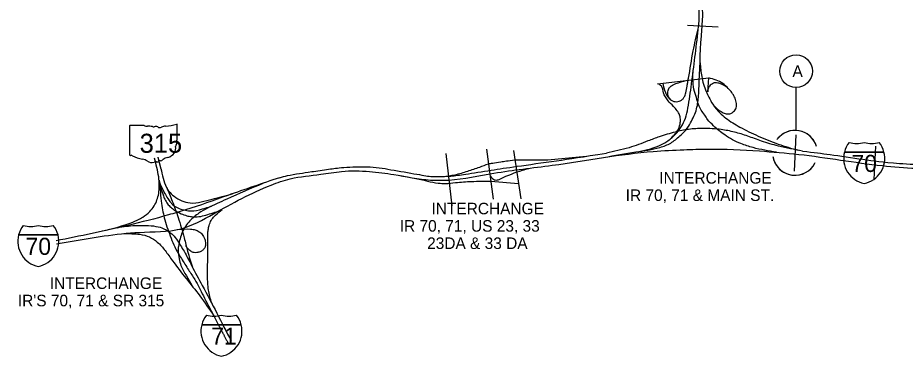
# Model space of a CAD drawing. Extents: x -13 to 322, y -402 to 112.
# Drawn here: x -2.76 to 6.02, y 97.23 to 100.58 of the extents above; entities that cross this region are included whole.
import ezdxf

# ---------------------------------------------------------------- set-up
doc = ezdxf.new("R2010")
doc.units = 0
for name, color, linetype in [('GM_X_Interstate_Shield', 7, 'Continuous'), ('GM_X_State_Shield', 7, 'Continuous'), ('SC_Scratch1', 7, 'Continuous'), ('SH_Data', 7, 'Continuous'), ('SH_Text', 7, 'Continuous')]:
    doc.layers.add(name, color=color, linetype=linetype)

msp = doc.modelspace()

# ---------------------------------------------------------------- linework, layer by layer
at = {"layer": 'GM_X_Interstate_Shield'}
for p, q in [((5.4189, 99.2528), (5.8101, 99.2528)), ((5.8101, 99.2528), (5.4189, 99.2528)), ((5.8101, 99.2528), (5.4189, 99.2528)), ((-2.7567, 98.4325), (-2.3655, 98.4325)), ((-2.3655, 98.4325), (-2.7567, 98.4325)), ((-2.3655, 98.4325), (-2.7567, 98.4325)), ((-0.9437, 97.5438), (-0.5525, 97.5438)), ((-0.5525, 97.5438), (-0.9437, 97.5438)), ((-0.5525, 97.5438), (-0.9437, 97.5438))]:
    msp.add_line(p, q, dxfattribs=at)
for centre, start, end in [((5.6653, 99.1905), 141.66896, 165.80665), ((5.5402, 99.5912), 253.00908, 286.99093), ((5.6888, 99.5912), 253.00908, 286.99093), ((5.5637, 99.1905), 14.19335, 38.33104), ((5.6653, 99.1905), 165.80665, 258.46304), ((5.5637, 99.1905), 281.53696, 14.19335), ((-2.5103, 98.3702), 141.66896, 165.80665), ((-2.6354, 98.771), 253.00908, 286.99093), ((-2.4868, 98.771), 253.00908, 286.99093), ((-2.612, 98.3702), 14.19335, 38.33104), ((-2.5103, 98.3702), 165.80665, 258.46304), ((-2.612, 98.3702), 281.53696, 14.19335), ((-0.6972, 97.4815), 141.66896, 165.80665), ((-0.8224, 97.8823), 253.00908, 286.99093), ((-0.6738, 97.8823), 253.00908, 286.99093), ((-0.7989, 97.4815), 14.19335, 38.33104), ((-0.6972, 97.4815), 165.80665, 258.46304), ((-0.7989, 97.4815), 281.53696, 14.19335)]:
    msp.add_arc(centre, 0.2542, start, end, dxfattribs=at)
at = {"layer": 'GM_X_State_Shield'}
for p, q in [((-1.6568, 99.5119), (-1.6568, 99.2254)), ((-1.514, 99.5168), (-1.6522, 99.5168)), ((-1.185, 99.374), (-1.185, 99.5239)), ((-1.185, 99.3741), (-1.185, 99.374))]:
    msp.add_line(p, q, dxfattribs=at)
for centre, major_axis, start_param, end_param in [((-1.6514, 99.5125), (0.00547, 0), 1.712693, 3.28349), ((-1.4811, 99.5501), (0.053, 0), 4.042523, 4.731795), ((-1.4635, 99.3559), (0.1904, 0), 1.404758, 1.657858), ((-1.4203, 99.514), (0.0153, 0), 3.836095, 5.185415), ((-1.3978, 99.4808), (0.0318, 0), 0.950623, 2.079405), ((-1.3568, 99.5263), (0.0383, 0), 4.081561, 5.145723), ((-1.2892, 99.4293), (0.1007, 0), 1.699011, 2.107814), ((-1.3531, 99.9074), (0.5004, 0), 4.814394, 5.042369), ((-1.1902, 99.5245), (0.00525, 0), 6.141152, 7.989035), ((-1.1862, 99.363), (0.00813, 0), 1.883978, 3.671073), ((-1.1906, 99.3734), (0.00562, 0), 5.05454, 6.418171), ((-1.325, 99.2922), (0.1252, 0), 5.101752, 6.440018), ((-1.1661, 99.3113), (0.0355, 0), 2.387724, 3.262537), ((-1.2379, 99.3441), (0.0488, 0), 5.934695, 6.695948), ((-1.6514, 99.2247), (0.00552, 0), 3.00124, 4.508301), ((-1.6505, 99.254), (0.0421, 0), 4.665946, 4.897461), ((-1.6419, 99.2088), (0.0152, 0), 0.519207, 1.627899), ((-1.4503, 99.4662), (0.3614, 0), 4.195997, 4.488961), ((-1.2722, 99.1449), (0.0685, 0), 1.647645, 2.488434), ((-1.5581, 99.0966), (0.1131, 0), 0.823519, 1.323587), ((-1.4358, 99.2074), (0.0717, 0), 4.026481, 4.996735), ((-1.3943, 99.1083), (0.059, 0), 1.495662, 1.94098), ((-1.3891, 99.1859), (0.0382, 0), 4.691044, 5.507374), ((-1.3545, 99.1582), (0.0108, 0), 1.147584, 2.315152), ((-1.3591, 99.1976), (0.0404, 0), 4.937069, 5.64225)]:
    msp.add_ellipse(centre, major_axis=major_axis, ratio=0.8, start_param=start_param, end_param=end_param, dxfattribs=at)
at = {"layer": 'SC_Scratch1'}
for p, q in [((3.8643, 100.5081), (4.1678, 100.4907)), ((4.9386, 99.4251), (4.9196, 99.0654)), ((1.8765, 99.2808), (1.9403, 98.7879)), ((5.7276, 99.3108), (5.7101, 98.9807)), ((1.4733, 99.2382), (1.5339, 98.721)), ((2.1433, 99.267), (2.217, 98.7916))]:
    msp.add_line(p, q, dxfattribs=at)
at = {"layer": 'SH_Data'}
for p, q in [((3.5691, 99.9286), (4.0757, 99.9866)), ((4.0653, 99.8493), (4.0757, 99.9866)), ((2.4821, 99.1771), (2.8628, 99.2116)), ((2.1572, 99.1772), (2.4821, 99.1771)), ((1.9172, 98.9666), (2.1936, 98.9429))]:
    msp.add_line(p, q, dxfattribs=at)
msp.add_lwpolyline([(4.94, 99.4671), (4.94, 99.8923)], dxfattribs=at)
msp.add_circle((4.94, 100.0535), 0.1612, dxfattribs=at)
for start, end in [(16.48105, 141.99166), (19.89812, 139.38655), (143.15405, 143.91896), (189.64144, 334.30322), (196.86832, 332.2344)]:
    msp.add_arc((4.9291, 99.2452), 0.2221, start, end, dxfattribs=at)
for points in [[(3.9713, 100.4643), (3.9818, 100.5824), (3.9714, 100.7456), (3.9442, 101.0053)], [(3.0353, 99.2003), (3.3547, 99.2543), (3.5926, 99.299), (3.6997, 99.3426), (3.7893, 99.4124), (3.851, 99.4734), (3.8951, 99.5416), (3.9552, 99.6805), (3.9748, 99.8131), (3.9812, 99.9553), (4.0059, 100.4624)], [(3.3547, 99.2543), (3.5809, 99.3152), (3.6597, 99.3576), (3.7444, 99.426), (3.8024, 99.5034), (3.8456, 99.5889), (3.8693, 99.687), (3.9053, 99.9266), (3.9391, 100.1908), (3.9713, 100.4643)], [(3.6197, 99.9343), (3.6472, 99.8428), (3.6713, 99.8001), (3.6927, 99.7753), (3.7161, 99.7594), (3.743, 99.7519), (3.7695, 99.7519), (3.7933, 99.7602), (3.816, 99.7756), (3.8331, 99.798), (3.8495, 99.8382), (3.8621, 99.9042), (3.8673, 99.9425), (3.875, 99.9842), (3.922, 100.2543), (3.9722, 100.4737)], [(3.99, 100.136), (4.0066, 99.9992), (4.0491, 99.8526), (4.0764, 99.7952), (4.1148, 99.7282), (4.1838, 99.6423), (4.245, 99.5895), (4.3843, 99.5004), (4.5646, 99.4119), (4.7641, 99.3312), (4.9607, 99.2717)], [(4.7464, 99.2512), (4.514, 99.297), (4.3938, 99.3368), (4.2333, 99.4231), (4.1237, 99.5128), (4.0643, 99.5766), (4.0355, 99.618), (3.9743, 99.7223), (3.9589, 99.7747), (3.9353, 99.8523), (3.92, 99.9484), (3.9207, 100.0445)], [(4.1213, 99.7183), (4.1762, 99.6663), (4.2192, 99.6422), (4.258, 99.6309), (4.2933, 99.6342), (4.3217, 99.6536), (4.3473, 99.6902), (4.3473, 99.7481), (4.3313, 99.7964), (4.3047, 99.8413), (4.2695, 99.8822), (4.2144, 99.9326), (4.0757, 99.9866)], [(3.7004, 99.3866), (3.7757, 99.4829), (3.7943, 99.5443), (3.7943, 99.5918), (3.7815, 99.6324), (3.7634, 99.6612), (3.7254, 99.7053), (3.673, 99.7614), (3.6465, 99.8), (3.6272, 99.8386), (3.6071, 99.9055), (3.5691, 99.9286)], [(3.7035, 99.7665), (3.6788, 99.7999), (3.6704, 99.8268), (3.6704, 99.85), (3.6774, 99.8737), (3.695, 99.8988), (3.7229, 99.9183), (3.7762, 99.9396), (3.8487, 99.9606)], [(4.1294, 99.9365), (4.0986, 99.9212), (4.0724, 99.8879), (4.0653, 99.8493)], [(4.2606, 99.8922), (4.21, 99.9212), (4.1759, 99.9341), (4.1528, 99.9379), (4.135, 99.9379), (4.1294, 99.9365)], [(5.0035, 99.2628), (4.7647, 99.3128), (4.5984, 99.3617), (4.4617, 99.4107), (4.33, 99.4503), (4.2001, 99.4757), (4.0195, 99.4866), (3.876, 99.4773), (3.7426, 99.4503), (3.5865, 99.4048), (3.4743, 99.3626), (3.2869, 99.2959), (3.0623, 99.2434)], [(3.0353, 99.2003), (3.5265, 99.2595), (3.8298, 99.2759), (4.0647, 99.2826), (4.5776, 99.2636), (4.9676, 99.2301), (5.7941, 99.1189), (6.128, 99.0921), (6.8877, 99.0604), (7.4588, 99.0399), (8.2632, 99.0023), (9.2422, 98.9359)], [(-2.3825, 98.3436), (-1.9076, 98.4228), (-1.5627, 98.4586), (-1.1481, 98.4944), (-0.8277, 98.6414), (-0.2567, 98.926), (-0.0663, 98.9882), (0.2352, 99.0334), (0.4417, 99.0612), (0.7186, 99.0612), (0.9568, 99.031), (1.3227, 98.9765), (1.5029, 98.9765), (1.9475, 99.0432), (2.5266, 99.1226), (3.0353, 99.2003)], [(-1.9282, 98.4722), (-1.6258, 98.5605), (-1.5266, 98.6089), (-1.4577, 98.6645), (-1.4142, 98.7202), (-1.3694, 98.8423), (-1.3694, 99.0068), (-1.4105, 99.1931)], [(1.4408, 99.0103), (1.5637, 99.0288), (1.6906, 99.0655), (1.8088, 99.1045), (1.895, 99.1377)], [(-1.3474, 99.0914), (-1.2916, 98.9034), (-1.2684, 98.8648), (-1.2177, 98.8166), (-1.1412, 98.7711), (-1.0579, 98.7496), (-0.9479, 98.7599), (-0.8413, 98.7874), (-0.6375, 98.8404)], [(1.0237, 99.0214), (1.2928, 98.9659), (1.3976, 98.9456), (1.4708, 98.9423), (1.5684, 98.9505), (1.7279, 98.9621), (1.9172, 98.9666)], [(1.9091, 99.0292), (1.9276, 98.9983), (1.9438, 98.9832), (1.9621, 98.9769), (1.9839, 98.9769), (2.0148, 98.9884), (2.2329, 99.0736), (2.2955, 99.0909)], [(-0.1743, 98.9991), (-0.6859, 98.8238), (-1.1049, 98.6797), (-1.2717, 98.6311), (-1.673, 98.5272), (-2.3845, 98.3738)], [(-1.3641, 98.9745), (-1.3232, 98.8196), (-1.3031, 98.7743), (-1.2749, 98.7314), (-1.2409, 98.6996), (-1.212, 98.677), (-1.1476, 98.6431), (-1.0911, 98.6227), (-1.0436, 98.6138), (-0.9705, 98.6138), (-0.9013, 98.63), (-0.7621, 98.6737)], [(-1.363, 98.9627), (-1.34, 98.7432), (-1.3087, 98.5817), (-1.2468, 98.4008), (-1.2105, 98.3142), (-1.1446, 98.1992), (-1.0745, 98.087), (-1.012, 97.9909), (-0.9272, 97.831), (-0.824, 97.633)], [(-1.3536, 98.9347), (-1.3108, 98.8461), (-1.2795, 98.7924), (-1.2531, 98.7568), (-1.2278, 98.7312), (-1.1813, 98.701), (-1.1195, 98.6806), (-1.0611, 98.6714), (-1.0228, 98.6714), (-0.9082, 98.6992), (-0.8464, 98.7165)], [(-0.3382, 98.943), (-0.696, 98.7864), (-0.8861, 98.6974), (-0.9713, 98.6476), (-1.0608, 98.5718), (-1.1363, 98.458), (-1.1581, 98.3951), (-1.1738, 98.3192), (-1.1775, 98.2737), (-1.167, 98.1972), (-1.1495, 98.1306), (-1.094, 98.0267), (-1.0427, 97.9374)], [(-1.2924, 98.9061), (-1.2349, 98.7677), (-1.1773, 98.6061), (-1.1172, 98.4041), (-1.0836, 98.2713), (-1.0344, 98.1139)], [(-0.8314, 97.7282), (-0.8713, 97.8565), (-0.88, 97.9187), (-0.8862, 98.0206), (-0.8862, 98.0992), (-0.882, 98.2697), (-0.882, 98.4549), (-0.8777, 98.4939), (-0.8662, 98.539), (-0.8422, 98.5882), (-0.8063, 98.6285), (-0.7408, 98.6843)], [(-1.7773, 98.5047), (-1.6041, 98.5266), (-1.4947, 98.5266), (-1.3961, 98.5177), (-1.3176, 98.4938), (-1.2402, 98.443), (-1.2095, 98.4117), (-1.1528, 98.3285), (-1.1185, 98.2711), (-1.043, 98.1299), (-0.9381, 97.9337), (-0.6523, 97.3835)], [(-1.1859, 98.4873), (-1.0528, 98.4905), (-1.0068, 98.4829), (-0.9693, 98.4652), (-0.9391, 98.4379), (-0.9138, 98.392), (-0.9048, 98.3484), (-0.9048, 98.3341), (-0.9141, 98.3062), (-0.9327, 98.2832), (-0.9595, 98.2664), (-0.9909, 98.258), (-1.0196, 98.258), (-1.0502, 98.2713), (-1.0865, 98.3068), (-1.0992, 98.3298)], [(-1.7122, 98.4455), (-1.5559, 98.439), (-1.4604, 98.4125), (-1.3829, 98.3624), (-1.3063, 98.2792), (-1.233, 98.1775), (-0.9626, 97.8298), (-0.824, 97.633)]]:
    msp.add_spline(points, degree=3, dxfattribs=at)
for points, degree in [([(4.0059, 100.4624), (4.016, 100.5475), (4.019, 100.6494), (3.9981, 100.8295), (3.9907, 100.9186), (3.9812, 101.0092)], 3), ([(-1.3474, 99.0914), (-1.3563, 99.1283), (-1.3662, 99.1645), (-1.3743, 99.2011)], 2), ([(-0.1743, 98.9991), (-0.142, 99.0098), (-0.1087, 99.0186), (0.0337, 99.0428), (0.1271, 99.0568), (0.3285, 99.0849), (0.4295, 99.1014), (0.7404, 99.1143), (0.9446, 99.0749), (1.2458, 99.0243), (1.3419, 99.0053), (1.5379, 99.0151), (1.6389, 99.0297), (1.9381, 99.076), (2.1399, 99.1075), (2.5821, 99.168), (2.8223, 99.2044), (3.0623, 99.2434)], 3), ([(5.0035, 99.2628), (5.1248, 99.249), (5.2459, 99.2332), (5.6233, 99.1786), (5.8765, 99.1407), (6.6531, 99.1054), (7.1719, 99.0941), (8.2095, 99.0479), (8.7272, 99.0081), (9.2448, 98.973)], 3), ([(1.895, 99.1377), (1.9114, 99.1403), (1.9278, 99.1429), (2.0151, 99.1563), (2.0862, 99.1668), (2.1572, 99.1772)], 3), ([(-0.824, 97.633), (-0.7776, 97.5442), (-0.7314, 97.4553), (-0.6852, 97.3664)], 2)]:
    msp.add_open_spline(points, degree=degree, dxfattribs=at)

# ---------------------------------------------------------------- texts
at = {"layer": 'GM_X_Interstate_Shield'}
for s, p in [('70', (5.4885, 99.0558)), ('70', (-2.6871, 98.2355)), ('71', (-0.849, 97.3468))]:
    msp.add_text(s, height=0.16947, dxfattribs=at).set_placement(p)
at = {"layer": 'GM_X_State_Shield'}
msp.add_text('315', height=0.18875, dxfattribs=at).set_placement((-1.5579, 99.2456))
at = {"layer": 'SH_Data'}
msp.add_text('A', height=0.1144, dxfattribs=at).set_placement((4.9044, 99.9963))
at = {"layer": 'SH_Text'}
for s, p in [('INTERCHANGE', (3.586, 98.9404)), ('IR 70, 71 & MAIN ST.', (3.2537, 98.7689)), ('INTERCHANGE', (1.3311, 98.6368)), ('IR 70, 71, US 23, 33', (1.0169, 98.4652)), ('23DA & 33 DA', (1.2879, 98.2937)), ('INTERCHANGE', (-2.4476, 97.898)), ("IR'S 70, 71 & SR 315", (-2.7632, 97.7265))]:
    msp.add_text(s, height=0.114366, dxfattribs=at).set_placement(p)

doc.saveas('drawing.dxf')
